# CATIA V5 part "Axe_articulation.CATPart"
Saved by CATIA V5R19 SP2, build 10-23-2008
Part number: Axe_articulation
Bounding box of the stored display mesh (mm): x -33 to 65, y -299 to -289, z -149 to -139
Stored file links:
  G:\EU_thinkMotion\CFAO_2010\MMS_groupe3\MMS_groupe3\pmayet\pmayet_assemblage_animation\pmayet_assemblage_animation\Axe_articulation.CATPart
  G:\EU_thinkMotion\CFAO_2010\MMS_groupe3\MMS_groupe3\pmayet\pmayet_assemblage_animation\pmayet_assemblage_animation\pmayet_assemblage_animation.CATProduct
  G:\EU_thinkMotion\CFAO_2010\MMS_groupe3\MMS_groupe3\pmayet\pmayet_assemblage_animation\pmayet_assemblage_animation\Squelette_axe_articualtion.CATPart
  G:\EU_thinkMotion\CFAO_2010\MMS_groupe3\MMS_groupe3\pmayet\pmayet_assemblage_animation\pmayet_assemblage_animation\Biellette_b.CATPart
  G:\EU_thinkMotion\CFAO_2010\MMS_groupe3\MMS_groupe3\pmayet\pmayet_assemblage_animation\pmayet_assemblage_animation\Biellette_a.CATPart
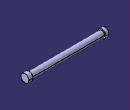
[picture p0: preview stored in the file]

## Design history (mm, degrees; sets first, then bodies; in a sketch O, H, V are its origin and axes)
Parameters
  Rayon_trou_biellette = 3.5 mm
  Longueur_axe = 49 mm
  Rayon_ext = 5 mm
Set1
  Plane1: linked copy from another document
  Point1 "Point.15_biellete_a": linked copy from another document
  DatumSurface1: linked copy from another document
  DatumSurface2: linked copy from another document
Body1 (main body)
  Sketch1 on Plane1, origin (16, 0, 0), H (0, -1, 0), V (0, 0, 1)
    circle A1 centre (294, -144) radius 3.5
    point P1 (294, -144)
    reference projected point E1 (294, -144) from Point1
    distance A1 P1 = 3.5 {= Rayon_trou_biellette}
    coincidence: P1 E1
  Pad1: profile Sketch1, direction (-1, 0, 0), length 49 {= Longueur_axe}, mirrored extent
  Sketch2 on start face of Pad1, origin (65, 0, 0), H (0, 1, 0), V (0, 0, 1)
    circle A1 centre (-294, -144) radius 5
    point P1 (-294, -144)
    reference projected circle E1 centre (-294, -144) radius 3.5 from edge [start face of Pad1 | face of Pad1 from Sketch1.A1]
    distance A1 P1 = 5 {= Rayon_ext}
    concentricity: E1 A1
  Pad2: profile Sketch2, direction (-1, 0, 0), up to face of DatumSurface1
  Sketch3 on end face of Pad1, origin (-33, 0, 0), H (0, -1, 0), V (0, 0, 1)
    circle A1 centre (294, -144) radius 5
    point P1 (294, -144)
    reference projected circle E1 centre (294, -144) radius 3.5 from edge [face of Pad1 from Sketch1.A1 | end face of Pad1]
    distance A1 P1 = 5 {= Rayon_ext}
    concentricity: E1 A1
  Pad3: profile Sketch3, direction (1, 0, 0), up to face of DatumSurface2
